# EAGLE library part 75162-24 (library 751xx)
75xxx DEVICE
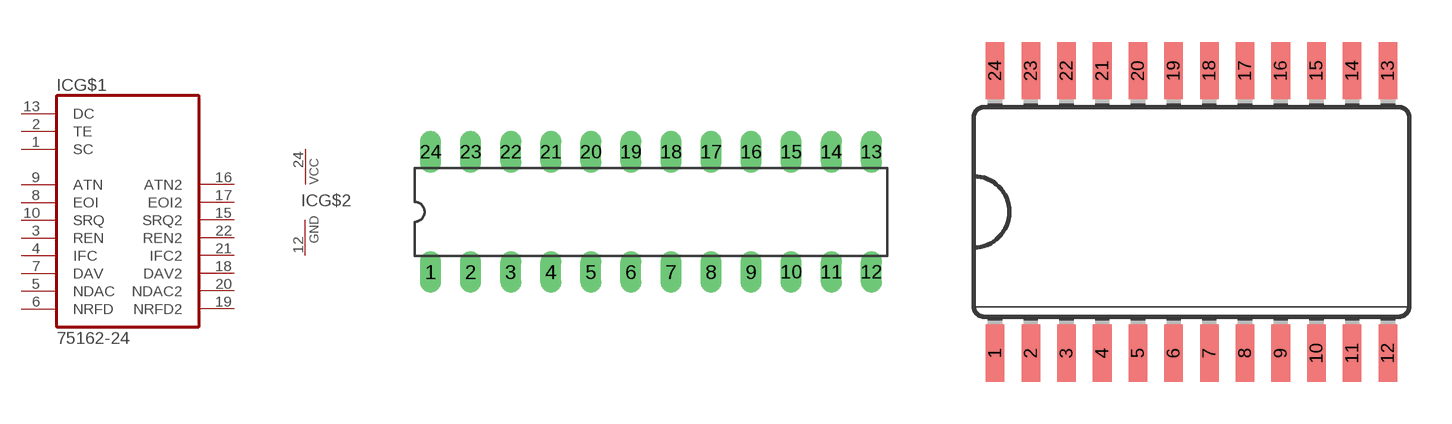
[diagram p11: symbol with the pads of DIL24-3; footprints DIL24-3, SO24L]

Designator prefix IC; gates G$1=75162-24 G$2=PWRN

## 75162-24P  [DIL24-3]
1  G$1:SC  in
2  G$1:TE  in
3  G$1:REN
4  G$1:IFC
5  G$1:NDAC
6  G$1:NRFD
7  G$1:DAV
8  G$1:EOI
9  G$1:ATN
10  G$1:SRQ
11  G$1:NC11  nc
12  G$2:GND  pwr
13  G$1:DC  in
14  G$1:NC14  nc
15  G$1:SRQ2
16  G$1:ATN2
17  G$1:EOI2
18  G$1:DAV2
19  G$1:NRFD2
20  G$1:NDAC2
21  G$1:IFC2
22  G$1:REN2
23  G$1:NC  nc
24  G$2:VCC  pwr

## 75162-24SO  [SO24L]
Pads as for DIL24-3

## Footprint DIL24-3 (pad centres in mm)
Dual In Line Package 0.3 inch
drill 0.813 long: 1 -13.97,-3.81; 2 -11.43,-3.81; 3 -8.89,-3.81; 4 -6.35,-3.81; 5 -3.81,-3.81; 6 -1.27,-3.81; 7 1.27,-3.81; 8 3.81,-3.81; 9 6.35,-3.81; 10 8.89,-3.81; 11 11.43,-3.81; 12 13.97,-3.81; 13 13.97,3.81; 14 11.43,3.81; 15 8.89,3.81; 16 6.35,3.81; 17 3.81,3.81; 18 1.27,3.81; 19 -1.27,3.81; 20 -3.81,3.81; 21 -6.35,3.81; 22 -8.89,3.81; 23 -11.43,3.81; 24 -13.97,3.81

## Footprint SO24L (pad centres in mm)
Small Outline package large
smd 0.66 x 2.032: 1 -6.985,-5.029; 2 -5.715,-5.029; 3 -4.445,-5.029; 4 -3.175,-5.029; 5 -1.905,-5.029; 6 -0.635,-5.029; 7 0.635,-5.029; 8 1.905,-5.029; 9 3.175,-5.029; 10 4.445,-5.029; 11 5.715,-5.029; 12 6.985,-5.029; 13 6.985,5.029; 14 5.715,5.029; 15 4.445,5.029; 16 3.175,5.029; 17 1.905,5.029; 18 0.635,5.029; 19 -0.635,5.029; 20 -1.905,5.029; 21 -3.175,5.029; 22 -4.445,5.029; 23 -5.715,5.029; 24 -6.985,5.029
